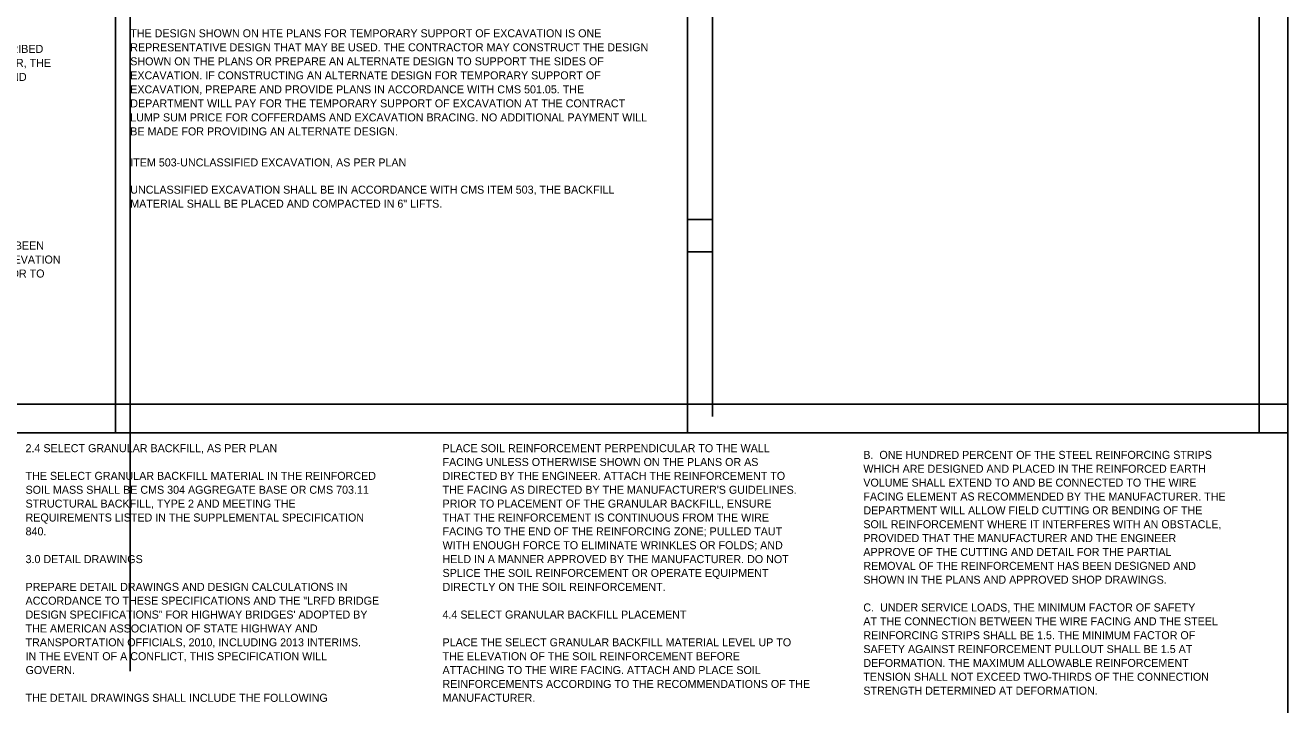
# Model space of a CAD drawing. Extents: x 1530552 to 1530730, y 675304 to 675366.
# Drawn here: x 1530563.61 to 1530585.69, y 675320.6 to 675332.48 of the extents above; entities that cross this region are included whole.
import ezdxf

# ---------------------------------------------------------------- set-up
doc = ezdxf.new("R2010")
doc.units = 0
for name, color, linetype in [('BR_P_Gen_Text', 7, 'Continuous'), ('SC_Scratch2', 7, 'Continuous'), ('SC_Scratch3', 7, 'Continuous')]:
    doc.layers.add(name, color=color, linetype=linetype)

msp = doc.modelspace()

# ---------------------------------------------------------------- linework, layer by layer
at = {"layer": 'BR_P_Gen_Text'}
for points in [[(1530555.188, 675346.353), (1530585.688, 675346.353), (1530585.688, 675325.353), (1530555.188, 675325.353)], [(1530555.188, 675325.353), (1530585.688, 675325.353), (1530585.688, 675304.353), (1530555.188, 675304.353)]]:
    msp.add_lwpolyline(points, close=True, dxfattribs=at)
at = {"layer": 'SC_Scratch2'}
for p, q in [((1530575.631, 675329.078), (1530575.194, 675329.078)), ((1530575.631, 675328.518), (1530575.194, 675328.518))]:
    msp.add_line(p, q, dxfattribs=at)
at = {"layer": 'SC_Scratch3'}
for p, q in [((1530565.447, 675321.188), (1530565.447, 675347.874)), ((1530565.188, 675325.353), (1530565.188, 675346.353)), ((1530575.189, 675325.353), (1530575.189, 675346.353)), ((1530575.631, 675325.636), (1530575.631, 675346.353)), ((1530585.188, 675346.353), (1530585.188, 675325.353)), ((1530555.188, 675325.853), (1530585.688, 675325.853))]:
    msp.add_line(p, q, dxfattribs=at)

# ---------------------------------------------------------------- texts
at = {"layer": 'BR_P_Gen_Text'}
for s, p in [('THE DESIGN SHOWN ON HTE PLANS FOR TEMPORARY SUPPORT OF EXCAVATION IS ONE ', (1530565.447, 675332.265)), ('BASE CONTRACT BID PRICES UPON A RECOGNITION OF THE UNCERTANTIES DESCRIBED', (1530555.688, 675331.992)), ('REPRESENTATIVE DESIGN THAT MAY BE USED. THE CONTRACTOR MAY CONSTRUCT THE DESIGN ', (1530565.447, 675332.02)), ('ABOVE AND UPON A PREBID EXAMINATION OF THE EXISTING STRUCTURE. HOWEVER, THE', (1530555.688, 675331.747)), ('SHOWN ON THE PLANS OR PREPARE AN ALTERNATE DESIGN TO SUPPORT THE SIDES OF ', (1530565.447, 675331.775)), ('DEPARTMENT WILL PAY FOR ALL PROJECT WORK BASED UPON ACTUAL DETAILS AND', (1530555.688, 675331.502)), ('EXCAVATION. IF CONSTRUCTING AN ALTERNATE DESIGN FOR TEMPORARY SUPPORT OF ', (1530565.447, 675331.53)), ('EXCAVATION, PREPARE AND PROVIDE PLANS IN ACCORDANCE WITH CMS 501.05. THE ', (1530565.447, 675331.285)), ('DEPARTMENT WILL PAY FOR THE TEMPORARY SUPPORT OF EXCAVATION AT THE CONTRACT ', (1530565.447, 675331.04)), ('LUMP SUM PRICE FOR COFFERDAMS AND EXCAVATION BRACING. NO ADDITIONAL PAYMENT WILL ', (1530565.447, 675330.795)), ('BE MADE FOR PROVIDING AN ALTERNATE DESIGN.', (1530565.447, 675330.55)), ('ITEM 503-UNCLASSIFIED EXCAVATION, AS PER PLAN', (1530565.447, 675330.008)), ('UNCLASSIFIED EXCAVATION SHALL BE IN ACCORDANCE WITH CMS ITEM 503, THE BACKFILL ', (1530565.447, 675329.532)), ('MATERIAL SHALL BE PLACED AND COMPACTED IN 6" LIFTS.', (1530565.447, 675329.287)), ('GRANULAR MATERIAL, 703.16.C. AFTER THE FOOTING AND THE BREASTWALL HAVE BEEN ', (1530555.688, 675328.556)), ('CONSTRUCTED, FILL THE VOID BEHIND EACH ABUTMENT UP TO THE BEAM SEAT ELEVATION ', (1530555.688, 675328.311)), ('AND FROM THE BEAM SEAT UP ON A 1:1 SLOPE TO THE SUBGRADE ELEVATION PRIOR TO ', (1530555.688, 675328.066)), ('2.4 SELECT GRANULAR BACKFILL, AS PER PLAN', (1530563.616, 675325.014)), ('PLACE SOIL REINFORCEMENT PERPENDICULAR TO THE WALL ', (1530570.908, 675325.014)), ('B.  ONE HUNDRED PERCENT OF THE STEEL REINFORCING STRIPS ', (1530578.267, 675324.897)), ('FACING UNLESS OTHERWISE SHOWN ON THE PLANS OR AS ', (1530570.908, 675324.772)), ('WHICH ARE DESIGNED AND PLACED IN THE REINFORCED EARTH ', (1530578.267, 675324.654)), ('THE SELECT GRANULAR BACKFILL MATERIAL IN THE REINFORCED ', (1530563.616, 675324.53)), ('DIRECTED BY THE ENGINEER. ATTACH THE REINFORCEMENT TO ', (1530570.908, 675324.53)), ('SOIL MASS SHALL BE CMS 304 AGGREGATE BASE OR CMS 703.11 ', (1530563.616, 675324.287)), ("THE FACING AS DIRECTED BY THE MANUFACTURER'S GUIDELINES. ", (1530570.908, 675324.287)), ('VOLUME SHALL EXTEND TO AND BE CONNECTED TO THE WIRE ', (1530578.267, 675324.412)), ('STRUCTURAL BACKFILL, TYPE 2 AND MEETING THE ', (1530563.616, 675324.045)), ('PRIOR TO PLACEMENT OF THE GRANULAR BACKFILL, ENSURE ', (1530570.908, 675324.045)), ('FACING ELEMENT AS RECOMMENDED BY THE MANUFACTURER. THE ', (1530578.267, 675324.169)), ('REQUIREMENTS LISTED IN THE SUPPLEMENTAL SPECIFICATION ', (1530563.616, 675323.802)), ('THAT THE REINFORCEMENT IS CONTINUOUS FROM THE WIRE ', (1530570.908, 675323.802)), ('DEPARTMENT WILL ALLOW FIELD CUTTING OR BENDING OF THE ', (1530578.267, 675323.927)), ('840.', (1530563.616, 675323.56)), ('FACING TO THE END OF THE REINFORCING ZONE; PULLED TAUT ', (1530570.908, 675323.56)), ('SOIL REINFORCEMENT WHERE IT INTERFERES WITH AN OBSTACLE, ', (1530578.267, 675323.685)), ('WITH ENOUGH FORCE TO ELIMINATE WRINKLES OR FOLDS; AND ', (1530570.908, 675323.318)), ('PROVIDED THAT THE MANUFACTURER AND THE ENGINEER ', (1530578.267, 675323.442)), ('APPROVE OF THE CUTTING AND DETAIL FOR THE PARTIAL ', (1530578.267, 675323.2)), ('3.0 DETAIL DRAWINGS', (1530563.616, 675323.075)), ('HELD IN A MANNER APPROVED BY THE MANUFACTURER. DO NOT ', (1530570.908, 675323.075)), ('REMOVAL OF THE REINFORCEMENT HAS BEEN DESIGNED AND ', (1530578.267, 675322.957)), ('SPLICE THE SOIL REINFORCEMENT OR OPERATE EQUIPMENT ', (1530570.908, 675322.833)), ('SHOWN IN THE PLANS AND APPROVED SHOP DRAWINGS.', (1530578.267, 675322.715)), ('PREPARE DETAIL DRAWINGS AND DESIGN CALCULATIONS IN ', (1530563.616, 675322.59)), ('DIRECTLY ON THE SOIL REINFORCEMENT.', (1530570.908, 675322.59)), ('ACCORDANCE TO THESE SPECIFICATIONS AND THE "LRFD BRIDGE ', (1530563.616, 675322.348)), ('C.  UNDER SERVICE LOADS, THE MINIMUM FACTOR OF SAFETY ', (1530578.267, 675322.23)), ('DESIGN SPECIFICATIONS" FOR HIGHWAY BRIDGES\' ADOPTED BY ', (1530563.616, 675322.106)), ('4.4 SELECT GRANULAR BACKFILL PLACEMENT', (1530570.908, 675322.106)), ('AT THE CONNECTION BETWEEN THE WIRE FACING AND THE STEEL ', (1530578.267, 675321.988)), ('THE AMERICAN ASSOCIATION OF STATE HIGHWAY AND ', (1530563.616, 675321.863)), ('TRANSPORTATION OFFICIALS, 2010, INCLUDING 2013 INTERIMS. ', (1530563.616, 675321.621)), ('PLACE THE SELECT GRANULAR BACKFILL MATERIAL LEVEL UP TO ', (1530570.908, 675321.621)), ('REINFORCING STRIPS SHALL BE 1.5. THE MINIMUM FACTOR OF ', (1530578.267, 675321.745)), ('IN THE EVENT OF A CONFLICT, THIS SPECIFICATION WILL ', (1530563.616, 675321.378)), ('THE ELEVATION OF THE SOIL REINFORCEMENT BEFORE ', (1530570.908, 675321.378)), ('SAFETY AGAINST REINFORCEMENT PULLOUT SHALL BE 1.5 AT ', (1530578.267, 675321.503)), ('GOVERN.', (1530563.616, 675321.136)), ('ATTACHING TO THE WIRE FACING. ATTACH AND PLACE SOIL ', (1530570.908, 675321.136)), ('DEFORMATION. THE MAXIMUM ALLOWABLE REINFORCEMENT ', (1530578.267, 675321.26)), ('REINFORCEMENTS ACCORDING TO THE RECOMMENDATIONS OF THE ', (1530570.908, 675320.893)), ('TENSION SHALL NOT EXCEED TWO-THIRDS OF THE CONNECTION ', (1530578.267, 675321.018)), ('STRENGTH DETERMINED AT DEFORMATION.', (1530578.267, 675320.776)), ('THE DETAIL DRAWINGS SHALL INCLUDE THE FOLLOWING ', (1530563.616, 675320.651)), ('MANUFACTURER.', (1530570.908, 675320.651))]:
    msp.add_text(s, height=0.14, dxfattribs=at).set_placement(p)

doc.saveas('drawing.dxf')
